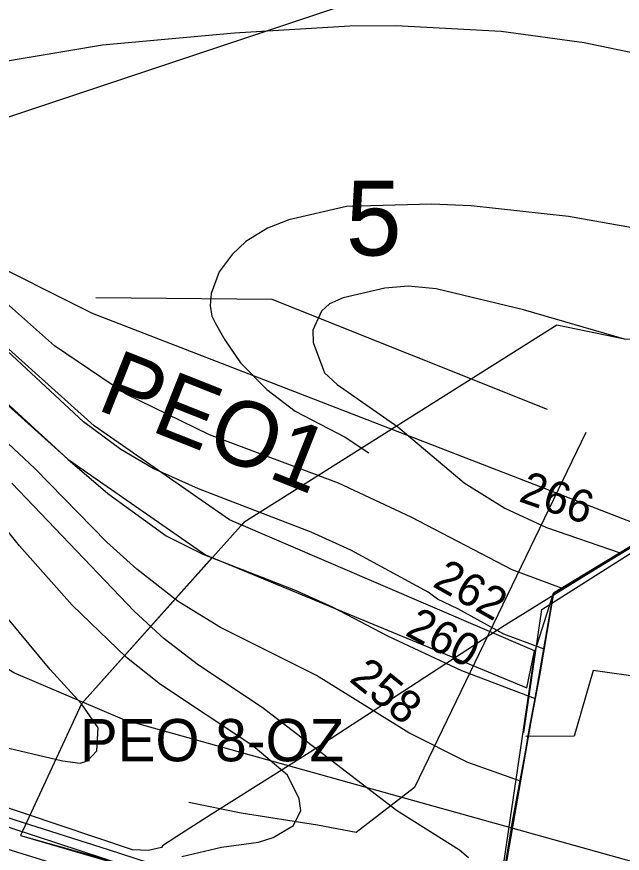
# Model space of a CAD drawing. Extents: x -662500 to -653478, y -1056827 to -1049993.
# Drawn here: x -660694.1 to -660508.3, y -1052097.9 to -1051840.9 of the extents above; entities that cross this region are included whole.
import ezdxf

# ---------------------------------------------------------------- set-up
doc = ezdxf.new("R2010")
doc.units = 0
for name, color, linetype in [('63LINIE', 7, 'Continuous'), ('Vrstva 1', 7, 'Continuous'), ('Vrstva 20', 7, 'Continuous'), ('Vrstva 22', 7, 'Continuous'), ('Vrstva 24', 7, 'Continuous'), ('Vrstva 45', 7, 'Continuous'), ('Vrstva 47', 7, 'Continuous'), ('Vrstva 48', 7, 'Continuous'), ('Vrstva 5', 7, 'Continuous'), ('Vrstva 57', 7, 'Continuous'), ('Vrstva 6', 7, 'Continuous'), ('Vrstva 7', 7, 'Continuous')]:
    doc.layers.add(name, color=color, linetype=linetype)

msp = doc.modelspace()

# ---------------------------------------------------------------- linework, layer by layer
at = {"layer": '63LINIE'}
msp.add_lwpolyline([(-661089.92, -1052023.41), (-661033.05, -1052031.56), (-660920.35, -1052046.48), (-660821, -1052060.23), (-660803.07, -1052062.71), (-660768.57, -1052074.37), (-660678.06, -1052102.44), (-660619.13, -1052120.72), (-660584.07, -1052131.59), (-660571.71, -1052135.42), (-660551.54, -1052138.42)], dxfattribs=at)
at = {"layer": 'Vrstva 1'}
msp.add_lwpolyline([(-660554.23, -1052145.33), (-660549.33, -1052132.73), (-660543.74, -1052100.07), (-660537.55, -1052064.32), (-660536.99, -1052061.08), (-660533.42, -1052042.18), (-660529.4, -1052017.99), (-660526.37, -1052016.17), (-660497.13, -1051998.48), (-660473.03, -1051983.91), (-660444.41, -1051966.62), (-660443.04, -1051941.53), (-660409.35, -1051945.41), (-660388.98, -1051947.77), (-660362.03, -1051950.34), (-660358.34, -1051950.81), (-660318.47, -1051954.21), (-660286.74, -1051956.91), (-660259.81, -1051958.85), (-660255.56, -1051959.16), (-660215.66, -1051962.04), (-660216.74, -1051952.44), (-660214.33, -1051927.93), (-660170.69, -1051923.36)], dxfattribs=at)
at = {"layer": 'Vrstva 20'}
msp.add_lwpolyline([(-660693, -1052092.39), (-660549.33, -1052132.73), (-660529.4, -1052017.99), (-660444.65, -1051966.93), (-660443.04, -1051941.53), (-660507.57, -1051940.01), (-660528.33, -1051935.72), (-660624.47, -1051996.3), (-660674.23, -1052051.96)], close=True, dxfattribs=at)
at = {"layer": 'Vrstva 22'}
msp.add_lwpolyline([(-660535.19, -1052035.73), (-660628.82, -1051995.51), (-660670.4, -1051966.64), (-660708.78, -1051932.15), (-660731.62, -1051914.69), (-660750.01, -1051903.34), (-660770.09, -1051895.71), (-660783.24, -1051893.57), (-660811.55, -1051893.32), (-660811.66, -1051906.32), (-660784.34, -1051906.56), (-660773.01, -1051908.4), (-660767.34, -1051910.1), (-660756, -1051914.92), (-660739, -1051925.41), (-660717.09, -1051942.16), (-660678.48, -1051976.85), (-660636.23, -1052006.19), (-660537.58, -1052047.09)], close=True, dxfattribs=at)
at = {"layer": 'Vrstva 24'}
for points in [[(-660809.04, -1051897.71), (-660805.5, -1051897.5), (-660775, -1051899), (-660742.5, -1051905.5), (-660707, -1051914), (-660671, -1051932), (-660495.5, -1052000)], [(-660328, -1052135), (-660352, -1052135.5), (-660451.5, -1052115.5), (-660661, -1052057), (-660695, -1052042.5), (-660723, -1052024.5), (-660747.5, -1052000), (-660756.5, -1051991), (-660777.56, -1051972.71)]]:
    msp.add_lwpolyline(points, dxfattribs=at)
at = {"layer": 'Vrstva 45'}
for points in [[(-660354.85, -1051915.03), (-660355.57, -1051915.05), (-660360.53, -1051915.59), (-660365.86, -1051916.12), (-660370.11, -1051918.64), (-660403.89, -1051941.33), (-660431.8, -1051959.98), (-660437.63, -1051964.09), (-660456.56, -1051977.17), (-660464.14, -1051981.81), (-660471.08, -1051986.06), (-660504.84, -1052003.55), (-660517.9, -1052011.55), (-660544.46, -1052028.03), (-660604.39, -1052067), (-660634.41, -1052086), (-660645.04, -1052092.71), (-660649.43, -1052095.57), (-660649.65, -1052096.13), (-660653.7, -1052096.98), (-660658.56, -1052096.83), (-660725, -1052074.48)], [(-660354.85, -1051915.03), (-660355.57, -1051915.05), (-660360.53, -1051915.59), (-660365.86, -1051916.12), (-660370.11, -1051918.64), (-660403.89, -1051941.33), (-660431.8, -1051959.98), (-660437.63, -1051964.09), (-660456.56, -1051977.17), (-660464.14, -1051981.81), (-660471.08, -1051986.06), (-660504.84, -1052003.55), (-660517.9, -1052011.55), (-660544.46, -1052028.03), (-660604.39, -1052067), (-660634.41, -1052086), (-660645.04, -1052092.71), (-660649.43, -1052095.57), (-660649.65, -1052096.13), (-660653.7, -1052096.98), (-660658.56, -1052096.83), (-660725, -1052074.48)], [(-660354.85, -1051915.03), (-660355.57, -1051915.05), (-660360.53, -1051915.59), (-660365.86, -1051916.12), (-660370.11, -1051918.64), (-660403.89, -1051941.33), (-660431.8, -1051959.98), (-660437.63, -1051964.09), (-660456.56, -1051977.17), (-660464.14, -1051981.81), (-660471.08, -1051986.06), (-660504.84, -1052003.55), (-660517.9, -1052011.55), (-660544.46, -1052028.03), (-660604.39, -1052067), (-660634.41, -1052086), (-660645.04, -1052092.71), (-660649.43, -1052095.57), (-660649.65, -1052096.13), (-660653.7, -1052096.98), (-660658.56, -1052096.83), (-660725, -1052074.48)], [(-660354.85, -1051915.03), (-660355.57, -1051915.05), (-660360.53, -1051915.59), (-660365.86, -1051916.12), (-660370.11, -1051918.64), (-660403.89, -1051941.33), (-660431.8, -1051959.98), (-660437.63, -1051964.09), (-660456.56, -1051977.17), (-660464.14, -1051981.81), (-660471.08, -1051986.06), (-660504.84, -1052003.55), (-660517.9, -1052011.55), (-660544.46, -1052028.03), (-660604.39, -1052067), (-660634.41, -1052086), (-660645.04, -1052092.71), (-660649.43, -1052095.57), (-660649.65, -1052096.13), (-660653.7, -1052096.98), (-660658.56, -1052096.83), (-660725, -1052074.48)], [(-660354.85, -1051915.03), (-660355.57, -1051915.05), (-660360.53, -1051915.59), (-660365.86, -1051916.12), (-660370.11, -1051918.64), (-660403.89, -1051941.33), (-660431.8, -1051959.98), (-660437.63, -1051964.09), (-660456.56, -1051977.17), (-660464.14, -1051981.81), (-660471.08, -1051986.06), (-660504.84, -1052003.55), (-660517.9, -1052011.55), (-660544.46, -1052028.03), (-660604.39, -1052067), (-660634.41, -1052086), (-660645.04, -1052092.71), (-660649.43, -1052095.57), (-660649.65, -1052096.13), (-660653.7, -1052096.98), (-660658.56, -1052096.83), (-660725, -1052074.48)], [(-660354.85, -1051915.03), (-660355.57, -1051915.05), (-660360.53, -1051915.59), (-660365.86, -1051916.12), (-660370.11, -1051918.64), (-660403.89, -1051941.33), (-660431.8, -1051959.98), (-660437.63, -1051964.09), (-660456.56, -1051977.17), (-660464.14, -1051981.81), (-660471.08, -1051986.06), (-660504.84, -1052003.55), (-660517.9, -1052011.55), (-660544.46, -1052028.03), (-660604.39, -1052067), (-660634.41, -1052086), (-660645.04, -1052092.71), (-660649.43, -1052095.57), (-660649.65, -1052096.13), (-660653.7, -1052096.98), (-660658.56, -1052096.83), (-660725, -1052074.48)], [(-660830.25, -1052048.16), (-660801.6, -1052052.43), (-660785.76, -1052056.82), (-660749.53, -1052069.14), (-660722.87, -1052078.18), (-660694.73, -1052087.6), (-660666.02, -1052096.71), (-660637.38, -1052105.99), (-660615.28, -1052112.88), (-660589.8, -1052120.12), (-660565.6, -1052125.72)], [(-660830.25, -1052048.16), (-660801.6, -1052052.43), (-660785.76, -1052056.82), (-660749.53, -1052069.14), (-660722.87, -1052078.18), (-660694.73, -1052087.6), (-660666.02, -1052096.71), (-660637.38, -1052105.99), (-660615.28, -1052112.88), (-660589.8, -1052120.12), (-660565.6, -1052125.72)]]:
    msp.add_lwpolyline(points, dxfattribs=at)
at = {"layer": 'Vrstva 47'}
msp.add_line((-659729.76, -1051549.11), (-661071.93, -1051997.01), dxfattribs=at)
at = {"layer": 'Vrstva 48'}
msp.add_lwpolyline([(-660538.48, -1052060.8), (-660532.95, -1052023.05), (-660419.09, -1051950.78), (-660293.14, -1051956.25), (-660296.06, -1052023.47), (-660343.35, -1052021.42), (-660365.15, -1052017.09), (-660400.6, -1052017.74), (-660407.59, -1052078.33), (-660450.39, -1052070.9), (-660455.11, -1052085.25), (-660475.19, -1052077.7), (-660472.89, -1052072.61), (-660501.35, -1052043.96), (-660517.23, -1052041.74), (-660522.98, -1052061.96), (-660537.85, -1052062.06)], dxfattribs=at)
at = {"layer": 'Vrstva 5'}
for points in [[(-660415.51, -1051792.48), (-660387.33, -1051842.39), (-660368.51, -1051881.97), (-660363.96, -1051894.27), (-660362.05, -1051903.98), (-660361.48, -1051911.34), (-660361.47, -1051915.93), (-660361.97, -1051944.48), (-660362.03, -1051950.34), (-660388.98, -1051947.77), (-660443.04, -1051941.53), (-660444.41, -1051966.62), (-660473.03, -1051983.91), (-660497.13, -1051998.48), (-660529.4, -1052017.99), (-660533.42, -1052042.18), (-660542.09, -1052088.13), (-660549.33, -1052132.73), (-660572.52, -1052128.33), (-660624.87, -1052113.48), (-660745.13, -1052073.98)], [(-660757.57, -1052084.94), (-660618.97, -1052129.25), (-660588.97, -1052137.76), (-660563.85, -1052144.19), (-660554.23, -1052145.33), (-660549.33, -1052132.73), (-660572.52, -1052128.33), (-660624.87, -1052113.48), (-660745.13, -1052073.98)]]:
    msp.add_lwpolyline(points, dxfattribs=at)
at = {"layer": 'Vrstva 57'}
for points in [[(-660531.17, -1051961.62), (-660615.76, -1051927.79), (-660669.81, -1051927.32)], [(-660519.42, -1051968.67), (-660572.05, -1052077.71), (-660589.91, -1052091.45), (-660601.78, -1052089.22), (-660625.28, -1052085.58), (-660641.26, -1052082.29)]]:
    msp.add_lwpolyline(points, dxfattribs=at)
at = {"layer": 'Vrstva 6'}
msp.add_lwpolyline([(-660717.09, -1051942.16), (-660678.48, -1051976.85), (-660636.23, -1052006.19), (-660634.2, -1052007.19), (-660674.23, -1052051.96), (-660693, -1052092.39), (-660616.69, -1052114.74), (-660549.33, -1052132.73), (-660535.03, -1052035.66), (-660529.4, -1052017.99), (-660444.79, -1051966.85), (-660443.04, -1051941.53), (-660507.57, -1051940.01), (-660528.33, -1051935.72), (-660624.47, -1051996.3), (-660625.14, -1051997.08), (-660628.82, -1051995.51), (-660670.4, -1051966.64), (-660708.78, -1051932.15)], dxfattribs=at)
at = {"layer": 'Vrstva 7'}
for p, q in [((-660627.32, -1051845.91), (-660591.89, -1051843.78)), ((-660591.89, -1051843.78), (-660577.72, -1051843.64)), ((-660577.72, -1051843.64), (-660545.41, -1051845.34)), ((-660667.85, -1051849.59), (-660627.32, -1051845.91)), ((-660545.41, -1051845.34), (-660519.9, -1051848.88)), ((-660519.9, -1051848.88), (-660481.64, -1051856.82)), ((-660715.75, -1051857.67), (-660667.85, -1051849.59)), ((-660592.88, -1051899.23), (-660610.6, -1051903.3)), ((-660566.67, -1051898.48), (-660592.88, -1051899.23)), ((-660554.62, -1051899.05), (-660566.67, -1051898.48)), ((-660524.72, -1051902.31), (-660554.62, -1051899.05)), ((-660486.88, -1051909.11), (-660524.72, -1051902.31)), ((-660610.6, -1051903.3), (-660617.12, -1051905.85)), ((-660617.12, -1051905.85), (-660623.78, -1051909.96)), ((-660623.78, -1051909.96), (-660628.03, -1051913.93)), ((-660628.03, -1051913.93), (-660632, -1051919.32)), ((-660632, -1051919.32), (-660634.5, -1051925.96)), ((-660682.59, -1051941.99), (-660704.42, -1051922.58)), ((-660634.5, -1051925.96), (-660634.74, -1051929.6)), ((-660581.12, -1051924.28), (-660593.88, -1051927.25)), ((-660574.01, -1051923.73), (-660581.12, -1051924.28)), ((-660565.39, -1051924.56), (-660574.01, -1051923.73)), ((-660538.61, -1051930.94), (-660565.39, -1051924.56)), ((-660593.88, -1051927.25), (-660598.13, -1051929.09)), ((-660634.74, -1051929.6), (-660634.27, -1051932.92)), ((-660598.13, -1051929.09), (-660600.54, -1051931.36)), ((-660507.57, -1051940.01), (-660538.61, -1051930.94)), ((-660634.27, -1051932.92), (-660633.24, -1051934.98)), ((-660600.54, -1051931.36), (-660603.21, -1051937.23)), ((-660633.24, -1051934.98), (-660630.25, -1051940.14)), ((-660673.66, -1051965.37), (-660704.7, -1051936.61)), ((-660603.21, -1051937.23), (-660603.1, -1051941)), ((-660630.25, -1051940.14), (-660625.48, -1051947.23)), ((-660603.1, -1051941), (-660599.69, -1051950.35)), ((-660660.77, -1051956.73), (-660682.59, -1051941.99)), ((-660708.53, -1051949.22), (-660678.48, -1051976.85)), ((-660625.48, -1051947.23), (-660617.4, -1051955.45)), ((-660599.69, -1051950.35), (-660595.72, -1051953.9)), ((-660688.54, -1051979.69), (-660718.31, -1051952.05)), ((-660595.72, -1051953.9), (-660577.16, -1051966.93)), ((-660634.98, -1051969.34), (-660660.77, -1051956.73)), ((-660617.4, -1051955.45), (-660608.62, -1051962.11)), ((-660608.62, -1051962.11), (-660593.31, -1051970.05)), ((-660662.19, -1051973.88), (-660673.66, -1051965.37)), ((-660577.16, -1051966.93), (-660556.75, -1051984.08)), ((-660595.41, -1051984.24), (-660634.98, -1051969.34)), ((-660593.31, -1051970.05), (-660586.08, -1051974.87)), ((-660652.27, -1051979.69), (-660662.19, -1051973.88)), ((-660678.48, -1051976.85), (-660666.15, -1051987.34)), ((-660666.44, -1052002.36), (-660688.54, -1051979.69)), ((-660638.38, -1051985.92), (-660652.27, -1051979.69)), ((-660693.24, -1052003.45), (-660708.67, -1051984.79)), ((-660658.08, -1052023.48), (-660695.63, -1051984.22)), ((-660573.1, -1051994.62), (-660595.41, -1051984.24)), ((-660556.75, -1051984.08), (-660544.28, -1051991.88)), ((-660666.15, -1051987.34), (-660648.3, -1052000.38)), ((-660603.8, -1051999.25), (-660638.38, -1051985.92)), ((-660544.28, -1051991.88), (-660531.52, -1051997.83)), ((-660542.01, -1052010.86), (-660573.1, -1051994.62)), ((-660531.52, -1051997.83), (-660508.93, -1052005.62)), ((-660648.3, -1052000.38), (-660636.96, -1052006.05)), ((-660591.61, -1052004.77), (-660603.8, -1051999.25)), ((-660657.22, -1052010.58), (-660666.44, -1052002.36)), ((-660677.07, -1052021.64), (-660693.24, -1052003.45)), ((-660567.8, -1052017.67), (-660591.61, -1052004.77)), ((-660636.96, -1052006.05), (-660608.62, -1052017.1)), ((-660644.61, -1052020.5), (-660657.22, -1052010.58)), ((-660526.91, -1052016.5), (-660542.01, -1052010.86)), ((-660608.62, -1052017.1), (-660597.28, -1052022.2)), ((-660564.92, -1052019.83), (-660567.8, -1052017.67)), ((-660631.58, -1052028.58), (-660644.61, -1052020.5)), ((-660558.73, -1052022.77), (-660564.92, -1052019.83)), ((-660660.48, -1052037.79), (-660677.07, -1052021.64)), ((-660648.86, -1052031.98), (-660658.08, -1052023.48)), ((-660597.28, -1052022.2), (-660580.27, -1052031.13)), ((-660544.56, -1052030.56), (-660558.73, -1052022.77)), ((-660683.87, -1052041.48), (-660696.76, -1052025.89)), ((-660602.1, -1052043.32), (-660631.58, -1052028.58)), ((-660580.27, -1052031.13), (-660557.6, -1052041.76)), ((-660532.27, -1052035.23), (-660544.56, -1052030.56)), ((-660638.38, -1052040.06), (-660648.86, -1052031.98)), ((-660650, -1052046.01), (-660660.48, -1052037.79)), ((-660674.23, -1052051.96), (-660683.87, -1052041.48)), ((-660618.82, -1052053.1), (-660638.38, -1052040.06)), ((-660573.75, -1052060.89), (-660602.1, -1052043.32)), ((-660557.6, -1052041.76), (-660534.97, -1052050.39)), ((-660621.66, -1052064.86), (-660650, -1052046.01)), ((-660669.13, -1052059.33), (-660674.23, -1052051.96)), ((-660577.58, -1052084.7), (-660618.82, -1052053.1)), ((-660669.56, -1052066.42), (-660669.13, -1052059.33)), ((-660555.61, -1052069.96), (-660573.75, -1052060.89)), ((-660701.58, -1052064.43), (-660680.04, -1052069.53)), ((-660611.03, -1052073.93), (-660621.66, -1052064.86)), ((-660672.39, -1052069.54), (-660669.56, -1052066.42)), ((-660680.04, -1052069.53), (-660674.66, -1052070.24)), ((-660674.66, -1052070.24), (-660672.39, -1052069.54)), ((-660539.53, -1052075.76), (-660555.61, -1052069.96)), ((-660607.48, -1052081.16), (-660611.03, -1052073.93)), ((-660606.92, -1052084.7), (-660607.48, -1052081.16)), ((-660609.18, -1052089.38), (-660606.92, -1052084.7)), ((-660558.17, -1052096.89), (-660577.58, -1052084.7)), ((-660615.42, -1052093.06), (-660609.18, -1052089.38)), ((-660619.95, -1052094.48), (-660615.42, -1052093.06)), ((-660631.29, -1052096.04), (-660619.95, -1052094.48)), ((-660643.48, -1052098.87), (-660631.29, -1052096.04)), ((-660555.47, -1052099.3), (-660558.17, -1052096.89))]:
    msp.add_line(p, q, dxfattribs=at)

# ---------------------------------------------------------------- texts
at = {"layer": 'Vrstva 20'}
msp.add_text('PEO 8-OZ', height=13, dxfattribs=at).set_placement((-660674.75, -1052069.64))
at = {"layer": 'Vrstva 22'}
msp.add_text('PEO1', height=20, rotation=338.3632, dxfattribs=at).set_placement((-660670.01, -1051961.43))
at = {"layer": 'Vrstva 57'}
msp.add_text('5', height=23, dxfattribs=at).set_placement((-660593.09, -1051914.28))
at = {"layer": 'Vrstva 7'}
for s, rotation, p in [('266', 340.9746, (-660540.36, -1051989.69)), ('262', 330.4608, (-660566.83, -1052015.74)), ('260', 332.1423, (-660575.29, -1052030.74)), ('258', 320.9645, (-660592.4, -1052044.8))]:
    msp.add_text(s, height=10, rotation=rotation, dxfattribs=at).set_placement(p)

doc.saveas('drawing.dxf')
